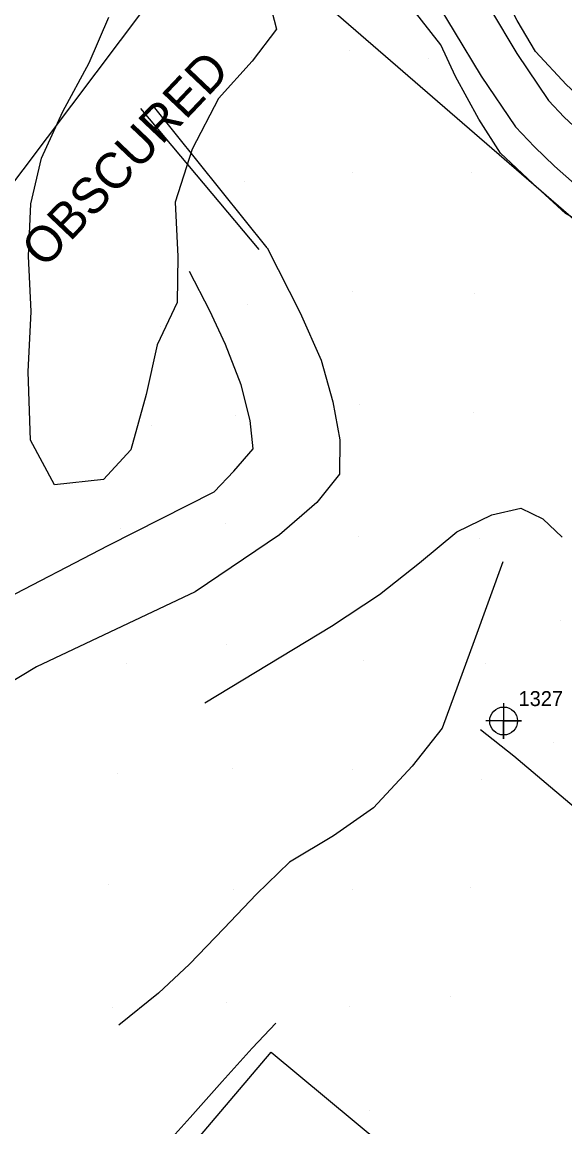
# Model space of a CAD drawing. Extents: x 1497074 to 1501343, y 481943 to 486114.
# Drawn here: x 1498512.5 to 1498603.4, y 484965.4 to 485150.3 of the extents above; entities that cross this region are included whole.
import ezdxf

# ---------------------------------------------------------------- set-up
doc = ezdxf.new("R2010")
doc.units = 0
for name, color, linetype in [('Exist DTM Regular Point CELL', 7, 'Continuous'), ('Exist DTM Regular Point Cogo Number', 7, 'Continuous'), ('PH Exist DTM Boundary', 7, 'Continuous'), ('PH Exist DTM Breakline', 7, 'Continuous'), ('PH Exist DTM Obscure Area', 7, 'Continuous'), ('PH Exist DTM Obscure Area Text', 7, 'Continuous'), ('PH Exist DTM Point', 7, 'Continuous')]:
    doc.layers.add(name, color=color, linetype=linetype)

msp = doc.modelspace()

# ---------------------------------------------------------------- linework, layer by layer
at = {"layer": 'Exist DTM Regular Point CELL'}
msp.add_lwpolyline([(1498593.11, 485036.3), (1498593.11, 485030.3), (1498593.11, 485033.3), (1498596.11, 485033.3), (1498590.11, 485033.3)], dxfattribs=at)
msp.add_circle((1498593.11, 485033.3), 2.34, dxfattribs=at)
at = {"layer": 'PH Exist DTM Boundary'}
for points in [[(1498924.23, 484841.06), (1498545.19, 485168.9), (1498846.5, 485569.16), (1499227.59, 485244.03)], [(1498186.43, 484771.69), (1498560.82, 484438.23), (1498782.89, 484653.31), (1498924.23, 484841.06), (1498545.19, 485168.9), (1498406.94, 484985.26)]]:
    msp.add_lwpolyline(points, close=True, dxfattribs=at)
at = {"layer": 'PH Exist DTM Breakline'}
for points in [[(1498643.25, 485116.12), (1498641.93, 485117.79), (1498630.19, 485123.26), (1498622.53, 485126.39), (1498617.07, 485128.84), (1498612.21, 485132), (1498607.96, 485135.81), (1498603.64, 485139.8), (1498598.46, 485145.39), (1498595.36, 485150.58), (1498592.75, 485155.81), (1498589.6, 485160.41), (1498585.1, 485164.63), (1498579.59, 485167.7), (1498575.08, 485170.11), (1498567.59, 485170.68), (1498562.35, 485172.69), (1498558.05, 485176.43), (1498549.24, 485182.41)], [(1498633.55, 485105.33), (1498624.45, 485108.81), (1498615.9, 485111.99), (1498609.49, 485114.84), (1498603.49, 485118.25), (1498598, 485123.27), (1498592.61, 485128.38), (1498588.98, 485134.07), (1498585.03, 485141.17), (1498582.59, 485146.51), (1498577.71, 485152.66), (1498572.01, 485156.75), (1498564.68, 485158.21), (1498558.97, 485159.65), (1498553.4, 485162.27), (1498546.6, 485165.4), (1498541.41, 485168.23), (1498535.25, 485173.22)], [(1498581.62, 485154.02), (1498584.84, 485148.74), (1498589.34, 485141.25), (1498595.08, 485132.75), (1498598.25, 485129.4), (1498601.63, 485126.19), (1498605.43, 485122.85), (1498610.04, 485120.77), (1498615.92, 485117.66), (1498622.04, 485115.68), (1498625.42, 485114.54), (1498629.71, 485112.64), (1498633.38, 485110.05), (1498635.97, 485108.47)], [(1498590.89, 485152.4), (1498595.31, 485145.06), (1498600.62, 485137.19), (1498603.25, 485134.4), (1498606.4, 485131.41), (1498609.31, 485128.87), (1498613.16, 485127.13), (1498618.69, 485124.2), (1498624.26, 485122.39), (1498627.98, 485121.14), (1498633.21, 485118.83), (1498640.92, 485114.32)], [(1498553.52, 485112.48), (1498534.25, 485136.51)], [(1498532.28, 485135.81), (1498552.14, 485112.2)], [(1498553.52, 485112.48), (1498559.03, 485101.62), (1498562.54, 485093.72), (1498564.51, 485086.74), (1498565.68, 485080.38), (1498565.6, 485074.64), (1498561.84, 485069.88), (1498555.57, 485064.48), (1498541.43, 485054.91), (1498514.86, 485042.38)], [(1498490.53, 485035.88), (1498508.58, 485053.2), (1498526.89, 485062.68), (1498544.63, 485071.64), (1498547.94, 485075.12), (1498551.17, 485078.85), (1498550.65, 485083.6), (1498549.18, 485089.59), (1498546.54, 485096.31), (1498543.93, 485101.96), (1498540.52, 485108.52)], [(1498543.06, 485036.32), (1498564.29, 485049.17), (1498572.3, 485054.48), (1498579, 485059.8), (1498585.28, 485064.95), (1498591.16, 485067.83), (1498595.97, 485068.9), (1498599.69, 485067.13), (1498602.92, 485064.06)], [(1498592.99, 485059.96), (1498588.15, 485046.72), (1498582.81, 485032.11), (1498577.78, 485025.74), (1498571.33, 485018.78), (1498564.6, 485014.07), (1498557.25, 485009.65), (1498551.7, 485004.33), (1498546.24, 484998.58), (1498540.51, 484992.57), (1498535.33, 484987.75), (1498528.7, 484982.36)], [(1498514.86, 485042.38), (1498502.56, 485034.92), (1498491.42, 485025.53), (1498488.22, 485020.95), (1498485.1, 485013.61), (1498483.54, 485005.52), (1498483, 484996.89), (1498482.86, 484989.45), (1498483.26, 484982.31), (1498484.35, 484975.02), (1498486.12, 484968.21), (1498487.65, 484962.18), (1498490.48, 484955.33), (1498494.88, 484948.44), (1498500.13, 484942.99)], [(1498643.27, 484967.43), (1498645.05, 484974.88), (1498646.42, 484980.62), (1498641.75, 484986.63), (1498631.6, 484996.33), (1498594.82, 485027.42), (1498589.22, 485031.84)], [(1498504.73, 484928.82), (1498508.31, 484932.52), (1498513.04, 484937.5), (1498519.02, 484943.8), (1498524.49, 484949.56), (1498530.25, 484955.67), (1498535.58, 484961.36), (1498540.62, 484966.93), (1498545.98, 484972.94), (1498551.02, 484978.56), (1498554.96, 484982.71)], [(1498505.34, 484923.95), (1498508.48, 484926.39), (1498513.83, 484930.78), (1498525.17, 484943.66), (1498554.18, 484977.87), (1498572.74, 484962.48)]]:
    msp.add_lwpolyline(points, dxfattribs=at)
at = {"layer": 'PH Exist DTM Obscure Area'}
msp.add_lwpolyline([(1498553.22, 485156.23), (1498555.08, 485149.12), (1498551.01, 485143.73), (1498545.38, 485137.48), (1498540.96, 485129.01), (1498538.12, 485120.15), (1498538.58, 485111.08), (1498538.42, 485103.36), (1498535.09, 485096.26), (1498533.24, 485087.95), (1498530.7, 485078.69), (1498526.09, 485073.72), (1498517.9, 485072.84), (1498513.86, 485080.29), (1498513.51, 485091.74), (1498514.01, 485101.86), (1498513.55, 485111.09), (1498513.96, 485119.86), (1498515.75, 485127.54), (1498519.29, 485135.35), (1498523.7, 485143.45), (1498526.99, 485151.13)], dxfattribs=at)
at = {"layer": 'PH Exist DTM Point'}
for p, q in [((1498567.36, 485145.59), (1498567.36, 485145.59)), ((1498550.94, 485144.38), (1498550.94, 485144.38)), ((1498580.57, 485144.12), (1498580.57, 485144.12)), ((1498567.81, 485125.16), (1498567.81, 485125.16)), ((1498587.81, 485125.16), (1498587.81, 485125.16)), ((1498549.69, 485123.59), (1498549.69, 485123.59)), ((1498567.81, 485105.16), (1498567.81, 485105.16)), ((1498588.18, 485104.81), (1498588.18, 485104.81)), ((1498550.14, 485102.95), (1498550.14, 485102.95)), ((1498535.71, 485099.33), (1498535.71, 485099.33)), ((1498568.9, 485086.31), (1498568.9, 485086.31)), ((1498548.19, 485084.42), (1498548.19, 485084.42)), ((1498588.07, 485084.92), (1498588.07, 485084.92)), ((1498534.11, 485082.74), (1498534.11, 485082.74)), ((1498546.61, 485066.3), (1498546.61, 485066.3)), ((1498528.92, 485065.58), (1498528.92, 485065.58)), ((1498568.86, 485064.17), (1498568.86, 485064.17)), ((1498589.14, 485063.9), (1498589.14, 485063.9)), ((1498602.67, 485050.04), (1498602.67, 485050.04)), ((1498546.75, 485046.17), (1498546.75, 485046.17)), ((1498530.04, 485042.95), (1498530.04, 485042.95)), ((1498569.72, 485043.35), (1498569.72, 485043.35)), ((1498590.13, 485042.96), (1498590.13, 485042.96)), ((1498601.42, 485029.68), (1498601.42, 485029.68)), ((1498547.66, 485025.3), (1498547.66, 485025.3)), ((1498567.81, 485025.16), (1498567.81, 485025.16)), ((1498528.47, 485024.54), (1498528.47, 485024.54)), ((1498589.48, 485023.57), (1498589.48, 485023.57)), ((1498526.91, 485006.01), (1498526.91, 485006.01)), ((1498547.91, 485005.07), (1498547.91, 485005.07)), ((1498567.82, 485005.15), (1498567.82, 485005.15)), ((1498587.57, 485005.39), (1498587.57, 485005.39)), ((1498584.13, 484987.14), (1498584.13, 484987.14)), ((1498527.61, 484985.35), (1498527.61, 484985.35)), ((1498546.73, 484986.19), (1498546.73, 484986.19)), ((1498567.36, 484985.59), (1498567.36, 484985.59)), ((1498570.64, 484968.14), (1498570.64, 484968.14))]:
    msp.add_line(p, q, dxfattribs=at)

# ---------------------------------------------------------------- texts
at = {"layer": 'Exist DTM Regular Point Cogo Number'}
msp.add_text('1327', height=2.5, dxfattribs=at).set_placement((1498595.61, 485035.8))
at = {"layer": 'PH Exist DTM Obscure Area Text'}
msp.add_text('OBSCURED', height=6, rotation=46.4845, dxfattribs=at).set_placement((1498516.21, 485108.9))

doc.saveas('drawing.dxf')
